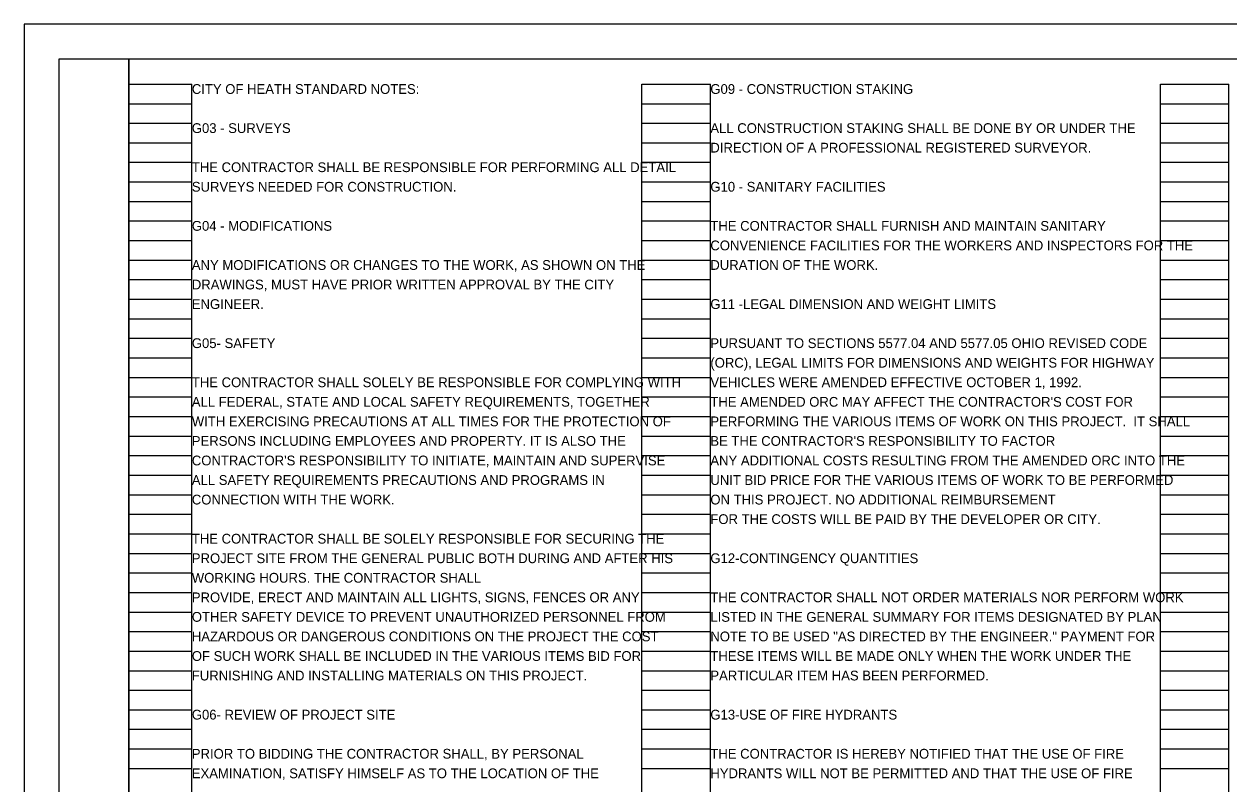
# Model space of a CAD drawing. Extents: x 0 to 37.1, y 0 to 22.
# Drawn here: x 0 to 17.24, y 11.12 to 22 of the extents above; entities that cross this region are included whole.
import ezdxf

# ---------------------------------------------------------------- set-up
doc = ezdxf.new("R2010")
doc.units = 0
for name, color, linetype in [('SH_Border', 7, 'Continuous'), ('SH_Cut_Line', 7, 'Continuous'), ('SH_Data', 7, 'Continuous'), ('SH_Text', 7, 'Continuous')]:
    doc.layers.add(name, color=color, linetype=linetype)

msp = doc.modelspace()

# ---------------------------------------------------------------- linework, layer by layer
at = {"layer": 'SH_Border'}
for points in [[(0.5, 21.5), (1.5, 21.5), (1.5, 0.5), (0.5, 0.5)], [(1.5, 21.5), (33.5, 21.5), (33.5, 0.5), (1.5, 0.5)]]:
    msp.add_lwpolyline(points, close=True, dxfattribs=at)
at = {"layer": 'SH_Cut_Line'}
msp.add_lwpolyline([(0, 0), (34, 0), (34, 22), (0, 22)], close=True, dxfattribs=at)
at = {"layer": 'SH_Data'}
for p, q in [((1.5, 0.98), (1.5, 21.14)), ((1.5, 21.14), (2.4, 21.14)), ((2.4, 0.98), (2.4, 21.14)), ((8.84, 0.98), (8.84, 21.14)), ((8.84, 21.14), (9.82, 21.14)), ((9.82, 0.98), (9.82, 21.14)), ((16.26, 0.98), (16.26, 21.14)), ((16.26, 21.14), (17.24, 21.14)), ((17.24, 0.98), (17.24, 21.14)), ((1.5, 20.86), (2.4, 20.86)), ((8.84, 20.86), (9.82, 20.86)), ((16.26, 20.86), (17.24, 20.86)), ((1.5, 20.58), (2.4, 20.58)), ((8.84, 20.58), (9.82, 20.58)), ((16.26, 20.58), (17.24, 20.58)), ((1.5, 20.3), (2.4, 20.3)), ((8.84, 20.3), (9.82, 20.3)), ((16.26, 20.3), (17.24, 20.3)), ((1.5, 20.02), (2.4, 20.02)), ((8.84, 20.02), (9.82, 20.02)), ((16.26, 20.02), (17.24, 20.02)), ((1.5, 19.74), (2.4, 19.74)), ((8.84, 19.74), (9.82, 19.74)), ((16.26, 19.74), (17.24, 19.74)), ((1.5, 19.46), (2.4, 19.46)), ((8.84, 19.46), (9.82, 19.46)), ((16.26, 19.46), (17.24, 19.46)), ((1.5, 19.18), (2.4, 19.18)), ((8.84, 19.18), (9.82, 19.18)), ((16.26, 19.18), (17.24, 19.18)), ((1.5, 18.9), (2.4, 18.9)), ((8.84, 18.9), (9.82, 18.9)), ((16.26, 18.9), (17.24, 18.9)), ((1.5, 18.62), (2.4, 18.62)), ((8.84, 18.62), (9.82, 18.62)), ((16.26, 18.62), (17.24, 18.62)), ((1.5, 18.34), (2.4, 18.34)), ((8.84, 18.34), (9.82, 18.34)), ((16.26, 18.34), (17.24, 18.34)), ((1.5, 18.06), (2.4, 18.06)), ((8.84, 18.06), (9.82, 18.06)), ((16.26, 18.06), (17.24, 18.06)), ((1.5, 17.78), (2.4, 17.78)), ((8.84, 17.78), (9.82, 17.78)), ((16.26, 17.78), (17.24, 17.78)), ((1.5, 17.5), (2.4, 17.5)), ((8.84, 17.5), (9.82, 17.5)), ((16.26, 17.5), (17.24, 17.5)), ((1.5, 17.22), (2.4, 17.22)), ((8.84, 17.22), (9.82, 17.22)), ((16.26, 17.22), (17.24, 17.22)), ((1.5, 16.94), (2.4, 16.94)), ((8.84, 16.94), (9.82, 16.94)), ((16.26, 16.94), (17.24, 16.94)), ((1.5, 16.66), (2.4, 16.66)), ((8.84, 16.66), (9.82, 16.66)), ((16.26, 16.66), (17.24, 16.66)), ((1.5, 16.38), (2.4, 16.38)), ((8.84, 16.38), (9.82, 16.38)), ((16.26, 16.38), (17.24, 16.38)), ((1.5, 16.1), (2.4, 16.1)), ((8.84, 16.1), (9.82, 16.1)), ((16.26, 16.1), (17.24, 16.1)), ((1.5, 15.82), (2.4, 15.82)), ((8.84, 15.82), (9.82, 15.82)), ((16.26, 15.82), (17.24, 15.82)), ((1.5, 15.54), (2.4, 15.54)), ((8.84, 15.54), (9.82, 15.54)), ((16.26, 15.54), (17.24, 15.54)), ((1.5, 15.26), (2.4, 15.26)), ((8.84, 15.26), (9.82, 15.26)), ((16.26, 15.26), (17.24, 15.26)), ((1.5, 14.98), (2.4, 14.98)), ((8.84, 14.98), (9.82, 14.98)), ((16.26, 14.98), (17.24, 14.98)), ((1.5, 14.7), (2.4, 14.7)), ((8.84, 14.7), (9.82, 14.7)), ((16.26, 14.7), (17.24, 14.7)), ((1.5, 14.42), (2.4, 14.42)), ((8.84, 14.42), (9.82, 14.42)), ((16.26, 14.42), (17.24, 14.42)), ((1.5, 14.14), (2.4, 14.14)), ((8.84, 14.14), (9.82, 14.14)), ((16.26, 14.14), (17.24, 14.14)), ((1.5, 13.86), (2.4, 13.86)), ((8.84, 13.86), (9.82, 13.86)), ((16.26, 13.86), (17.24, 13.86)), ((1.5, 13.58), (2.4, 13.58)), ((8.84, 13.58), (9.82, 13.58)), ((16.26, 13.58), (17.24, 13.58)), ((1.5, 13.3), (2.4, 13.3)), ((8.84, 13.3), (9.82, 13.3)), ((16.26, 13.3), (17.24, 13.3)), ((1.5, 13.02), (2.4, 13.02)), ((8.84, 13.02), (9.82, 13.02)), ((16.26, 13.02), (17.24, 13.02)), ((1.5, 12.74), (2.4, 12.74)), ((8.84, 12.74), (9.82, 12.74)), ((16.26, 12.74), (17.24, 12.74)), ((1.5, 12.46), (2.4, 12.46)), ((8.84, 12.46), (9.82, 12.46)), ((16.26, 12.46), (17.24, 12.46)), ((1.5, 12.18), (2.4, 12.18)), ((8.84, 12.18), (9.82, 12.18)), ((16.26, 12.18), (17.24, 12.18)), ((1.5, 11.9), (2.4, 11.9)), ((8.84, 11.9), (9.82, 11.9)), ((16.26, 11.9), (17.24, 11.9)), ((1.5, 11.62), (2.4, 11.62)), ((8.84, 11.62), (9.82, 11.62)), ((16.26, 11.62), (17.24, 11.62)), ((1.5, 11.34), (2.4, 11.34)), ((8.84, 11.34), (9.82, 11.34)), ((16.26, 11.34), (17.24, 11.34))]:
    msp.add_line(p, q, dxfattribs=at)

# ---------------------------------------------------------------- texts
at = {"layer": 'SH_Text'}
for s, p in [('CITY OF HEATH STANDARD NOTES:', (2.4, 21)), ('G09 - CONSTRUCTION STAKING', (9.82, 21)), ('G03 - SURVEYS', (2.4, 20.44)), ('ALL CONSTRUCTION STAKING SHALL BE DONE BY OR UNDER THE ', (9.82, 20.44)), ('DIRECTION OF A PROFESSIONAL REGISTERED SURVEYOR.    ', (9.82, 20.16)), ('THE CONTRACTOR SHALL BE RESPONSIBLE FOR PERFORMING ALL DETAIL ', (2.4, 19.88)), ('SURVEYS NEEDED FOR CONSTRUCTION.', (2.4, 19.6)), ('G10 - SANITARY FACILITIES', (9.82, 19.6)), ('G04 - MODIFICATIONS', (2.4, 19.04)), ('THE CONTRACTOR SHALL FURNISH AND MAINTAIN SANITARY ', (9.82, 19.04)), ('CONVENIENCE FACILITIES FOR THE WORKERS AND INSPECTORS FOR THE ', (9.82, 18.76)), ('ANY MODIFICATIONS OR CHANGES TO THE WORK, AS SHOWN ON THE ', (2.4, 18.48)), ('DURATION OF THE WORK.  ', (9.82, 18.48)), ('DRAWINGS, MUST HAVE PRIOR WRITTEN APPROVAL BY THE CITY ', (2.4, 18.2)), ('ENGINEER.', (2.4, 17.92)), ('G11 -LEGAL DIMENSION AND WEIGHT LIMITS', (9.82, 17.92)), ('G05- SAFETY', (2.4, 17.36)), ('PURSUANT TO SECTIONS 5577.04 AND 5577.05 OHIO REVISED CODE ', (9.82, 17.36)), ('(ORC), LEGAL LIMITS FOR DIMENSIONS AND WEIGHTS FOR HIGHWAY ', (9.82, 17.08)), ('THE CONTRACTOR SHALL SOLELY BE RESPONSIBLE FOR COMPLYING WITH ', (2.4, 16.8)), ('VEHICLES WERE AMENDED EFFECTIVE OCTOBER 1, 1992.', (9.82, 16.8)), ('ALL FEDERAL, STATE AND LOCAL SAFETY REQUIREMENTS, TOGETHER ', (2.4, 16.52)), ("THE AMENDED ORC MAY AFFECT THE CONTRACTOR'S COST FOR ", (9.82, 16.52)), ('WITH EXERCISING PRECAUTIONS AT ALL TIMES FOR THE PROTECTION OF ', (2.4, 16.24)), ('PERFORMING THE VARIOUS ITEMS OF WORK ON THIS PROJECT.  IT SHALL ', (9.82, 16.24)), ('PERSONS INCLUDING EMPLOYEES AND PROPERTY. IT IS ALSO THE ', (2.4, 15.96)), ("BE THE CONTRACTOR'S RESPONSIBILITY TO FACTOR", (9.82, 15.96)), ("CONTRACTOR'S RESPONSIBILITY TO INITIATE, MAINTAIN AND SUPERVISE ", (2.4, 15.68)), ('ANY ADDITIONAL COSTS RESULTING FROM THE AMENDED ORC INTO THE ', (9.82, 15.68)), ('ALL SAFETY REQUIREMENTS PRECAUTIONS AND PROGRAMS IN ', (2.4, 15.4)), ('UNIT BID PRICE FOR THE VARIOUS ITEMS OF WORK TO BE PERFORMED ', (9.82, 15.4)), ('CONNECTION WITH THE WORK.', (2.4, 15.12)), ('ON THIS PROJECT. NO ADDITIONAL REIMBURSEMENT', (9.82, 15.12)), ('FOR THE COSTS WILL BE PAID BY THE DEVELOPER OR CITY.', (9.82, 14.84)), ('THE CONTRACTOR SHALL BE SOLELY RESPONSIBLE FOR SECURING THE ', (2.4, 14.56)), ('PROJECT SITE FROM THE GENERAL PUBLIC BOTH DURING AND AFTER HIS ', (2.4, 14.28)), ('G12-CONTINGENCY QUANTITIES', (9.82, 14.28)), ('WORKING HOURS. THE CONTRACTOR SHALL ', (2.4, 14)), ('PROVIDE, ERECT AND MAINTAIN ALL LIGHTS, SIGNS, FENCES OR ANY ', (2.4, 13.72)), ('THE CONTRACTOR SHALL NOT ORDER MATERIALS NOR PERFORM WORK ', (9.82, 13.72)), ('OTHER SAFETY DEVICE TO PREVENT UNAUTHORIZED PERSONNEL FROM ', (2.4, 13.44)), ('LISTED IN THE GENERAL SUMMARY FOR ITEMS DESIGNATED BY PLAN ', (9.82, 13.44)), ('HAZARDOUS OR DANGEROUS CONDITIONS ON THE PROJECT THE COST ', (2.4, 13.16)), ('NOTE TO BE USED "AS DIRECTED BY THE ENGINEER." PAYMENT FOR ', (9.82, 13.16)), ('OF SUCH WORK SHALL BE INCLUDED IN THE VARIOUS ITEMS BID FOR ', (2.4, 12.88)), ('THESE ITEMS WILL BE MADE ONLY WHEN THE WORK UNDER THE ', (9.82, 12.88)), ('FURNISHING AND INSTALLING MATERIALS ON THIS PROJECT.', (2.4, 12.6)), ('PARTICULAR ITEM HAS BEEN PERFORMED.', (9.82, 12.6)), ('G06- REVIEW OF PROJECT SITE', (2.4, 12.04)), ('G13-USE OF FIRE HYDRANTS', (9.82, 12.04)), ('PRIOR TO BIDDING THE CONTRACTOR SHALL, BY PERSONAL ', (2.4, 11.48)), ('THE CONTRACTOR IS HEREBY NOTIFIED THAT THE USE OF FIRE ', (9.82, 11.48)), ('EXAMINATION, SATISFY HIMSELF AS TO THE LOCATION OF THE ', (2.4, 11.2)), ('HYDRANTS WILL NOT BE PERMITTED AND THAT THE USE OF FIRE ', (9.82, 11.2))]:
    msp.add_text(s, height=0.14, dxfattribs=at).set_placement(p)

doc.saveas('drawing.dxf')
